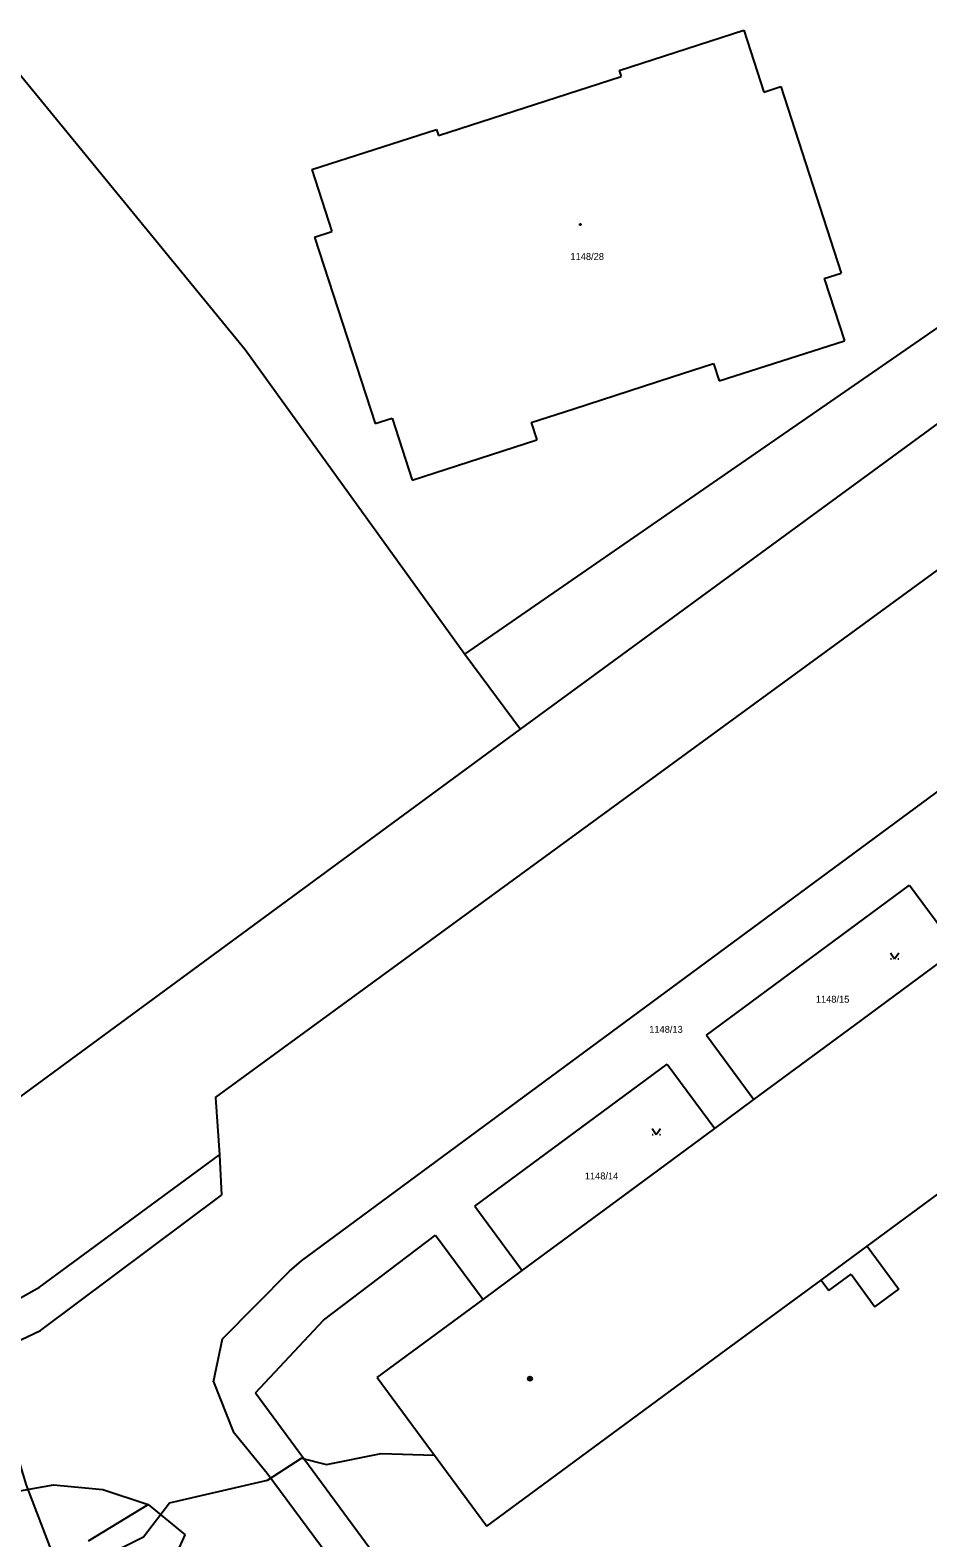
# Model space of a CAD drawing. Extents: x -609709 to -609357, y -1051535 to -1051131.
# Drawn here: x -609496.9 to -609441.9, y -1051248 to -1051155.6 of the extents above; entities that cross this region are included whole.
import ezdxf

# ---------------------------------------------------------------- set-up
doc = ezdxf.new("R2010")
doc.units = 0
doc.layers.add('Vrstva 10', color=7, linetype='Continuous')
doc.layers.add('Vrstva 15', color=7, linetype='Continuous')

msp = doc.modelspace()

# ---------------------------------------------------------------- linework, layer by layer
at = {"layer": 'Vrstva 10'}
for p, q in [((-609460.81, -1051158.03), (-609453.17, -1051155.56)), ((-609453.17, -1051155.56), (-609451.94, -1051159.36)), ((-609497.6, -1051158.2), (-609483.73, -1051175.13)), ((-609460.81, -1051158.03), (-609460.69, -1051158.4)), ((-609471.88, -1051162.02), (-609460.69, -1051158.4)), ((-609451.94, -1051159.36), (-609450.89, -1051159.02)), ((-609450.89, -1051159.02), (-609447.19, -1051170.45)), ((-609479.64, -1051164.11), (-609472.01, -1051161.66)), ((-609472.01, -1051161.66), (-609471.88, -1051162.02)), ((-609470.26, -1051193.81), (-609425.78, -1051163.1)), ((-609479.64, -1051164.11), (-609478.41, -1051167.91)), ((-609466.85, -1051198.42), (-609424.18, -1051167.15)), ((-609463.225, -1051167.445), (-609463.15, -1051167.445)), ((-609463.225, -1051167.52), (-609463.225, -1051167.445)), ((-609463.15, -1051167.52), (-609463.225, -1051167.52)), ((-609463.15, -1051167.445), (-609463.15, -1051167.52)), ((-609479.47, -1051168.26), (-609478.41, -1051167.91)), ((-609479.47, -1051168.26), (-609475.76, -1051179.68)), ((-609448.23, -1051170.78), (-609447.19, -1051170.45)), ((-609448.23, -1051170.78), (-609447, -1051174.6)), ((-609454.67, -1051177.07), (-609447, -1051174.6)), ((-609483.73, -1051175.13), (-609470.26, -1051193.81)), ((-609457.62, -1051176.84), (-609455.02, -1051176)), ((-609455.02, -1051176), (-609454.67, -1051177.07)), ((-609463.59, -1051178.77), (-609457.62, -1051176.84)), ((-609485.54, -1051221), (-609428.85, -1051179.57)), ((-609475.76, -1051179.68), (-609474.72, -1051179.34)), ((-609474.72, -1051179.34), (-609473.49, -1051183.15)), ((-609466.2, -1051179.61), (-609463.59, -1051178.77)), ((-609466.2, -1051179.61), (-609465.86, -1051180.68)), ((-609473.49, -1051183.15), (-609465.86, -1051180.68)), ((-609480.28, -1051231.01), (-609423.49, -1051189.11)), ((-609470.26, -1051193.81), (-609466.85, -1051198.42)), ((-609498.87, -1051221.94), (-609466.85, -1051198.42)), ((-609455.45, -1051217.17), (-609443, -1051207.98)), ((-609443, -1051207.98), (-609440.08, -1051211.92)), ((-609446.36, -1051216.56), (-609440.08, -1051211.92)), ((-609444.17, -1051212.125), (-609443.92, -1051212.5)), ((-609444.17, -1051212.5), (-609444.12, -1051212.5)), ((-609443.92, -1051212.5), (-609443.67, -1051212.125)), ((-609443.72, -1051212.5), (-609443.67, -1051212.5)), ((-609452.54, -1051221.12), (-609446.36, -1051216.56)), ((-609455.45, -1051217.17), (-609452.54, -1051221.12)), ((-609469.66, -1051227.66), (-609457.86, -1051218.95)), ((-609457.86, -1051218.95), (-609454.94, -1051222.9)), ((-609485.54, -1051221), (-609485.31, -1051224.51)), ((-609454.94, -1051222.9), (-609452.54, -1051221.12)), ((-609460.94, -1051227.33), (-609454.94, -1051222.9)), ((-609458.78, -1051222.895), (-609458.53, -1051223.27)), ((-609458.53, -1051223.27), (-609458.28, -1051222.895)), ((-609458.78, -1051223.27), (-609458.73, -1051223.27)), ((-609458.33, -1051223.27), (-609458.28, -1051223.27)), ((-609496.33, -1051232.63), (-609485.31, -1051224.51)), ((-609485.31, -1051224.51), (-609485.18, -1051226.98)), ((-609445.6, -1051230.11), (-609439.61, -1051225.7)), ((-609496.28, -1051235.29), (-609485.18, -1051226.98)), ((-609469.66, -1051227.66), (-609466.74, -1051231.61)), ((-609466.74, -1051231.61), (-609460.94, -1051227.33)), ((-609478.93, -1051234.66), (-609472.07, -1051229.44)), ((-609472.07, -1051229.44), (-609469.15, -1051233.39)), ((-609448.43, -1051232.2), (-609445.6, -1051230.11)), ((-609445.6, -1051230.11), (-609443.66, -1051232.75)), ((-609481.01, -1051231.64), (-609480.28, -1051231.01)), ((-609485.12, -1051235.79), (-609481.01, -1051231.64)), ((-609469.15, -1051233.39), (-609466.74, -1051231.61)), ((-609454.24, -1051236.47), (-609448.43, -1051232.2)), ((-609448.43, -1051232.2), (-609447.96, -1051232.84)), ((-609447.96, -1051232.84), (-609446.59, -1051231.84)), ((-609446.59, -1051231.84), (-609445.13, -1051233.83)), ((-609499.6, -1051234.45), (-609496.33, -1051232.63)), ((-609445.13, -1051233.83), (-609443.66, -1051232.75)), ((-609475.63, -1051238.17), (-609469.15, -1051233.39)), ((-609483.09, -1051239.11), (-609478.93, -1051234.66)), ((-609499.02, -1051236.58), (-609496.28, -1051235.29)), ((-609485.67, -1051238.44), (-609485.12, -1051235.79)), ((-609468.91, -1051247.28), (-609454.24, -1051236.47)), ((-609485.67, -1051238.44), (-609484.46, -1051241.47)), ((-609475.63, -1051238.17), (-609468.91, -1051247.28)), ((-609483.09, -1051239.11), (-609463.77, -1051265.35)), ((-609484.46, -1051241.47), (-609482.39, -1051244.03)), ((-609482.39, -1051244.03), (-609464.32, -1051268.37)), ((-609498.45, -1051245.29), (-609495.48, -1051244.74)), ((-609495.48, -1051244.74), (-609492.46, -1051245.04)), ((-609492.46, -1051245.04), (-609489.67, -1051245.95)), ((-609493.34, -1051248.18), (-609489.67, -1051245.95)), ((-609489.67, -1051245.95), (-609487.4, -1051247.82)), ((-609489.74, -1051252.97), (-609487.4, -1051247.82))]:
    msp.add_line(p, q, dxfattribs=at)
for radius in [0.125, 0.0025]:
    msp.add_circle((-609466.27, -1051238.24), radius, dxfattribs=at)
at = {"layer": 'Vrstva 15'}
msp.add_lwpolyline([(-609521.08, -1051202.07), (-609519.34, -1051204.67), (-609514.81, -1051210.66), (-609514.03, -1051211.19), (-609512.3, -1051214.35), (-609507.99, -1051219.96), (-609504.74, -1051225.1), (-609501.77, -1051230.87), (-609499.14, -1051236.87), (-609498.5, -1051240.32), (-609497.15, -1051244.76), (-609494.99, -1051250.43), (-609489.96, -1051247.93), (-609488.37, -1051245.86), (-609482.36, -1051244.46), (-609480.27, -1051243.11), (-609478.75, -1051243.5), (-609475.39, -1051242.82), (-609472.143, -1051242.924)], dxfattribs=at)

# ---------------------------------------------------------------- texts
at = {"layer": 'Vrstva 10'}
for s, p in [('1148/28', (-609463.79, -1051169.65)), ('1148/15', (-609448.75, -1051215.19)), ('1148/13', (-609458.96, -1051217.035)), ('1148/14', (-609462.91, -1051226.025))]:
    msp.add_text(s, height=0.425, dxfattribs=at).set_placement(p)

doc.saveas('drawing.dxf')
